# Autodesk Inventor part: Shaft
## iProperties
Created: 2010-01
Part Number: Shaft
Material: Steel
Document SubType Name: Modeling
Designer: a31883
Density: 1 g/cm^3
CustomPartVersion: 1
Author: a31883
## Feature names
1. Revolution1
2. Chamfer1
